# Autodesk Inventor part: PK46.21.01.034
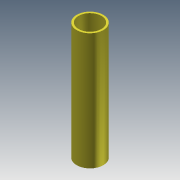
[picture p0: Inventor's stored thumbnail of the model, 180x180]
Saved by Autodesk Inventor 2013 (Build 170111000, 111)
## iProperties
Created: 2005-04
Part Number: PK46.21.01.034
Material: Steel, Mild
Document SubType Name: Modeling
Designer: salex
Manufacturer: Standard
Standards Organization: Custom
Density: 7.86 g/cm^3
Author: salex
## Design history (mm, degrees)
sketch "Эскиз1"
  geometry: C1 r 25 at (0, 0); C2 r 21.5 at (0, 0)
  constraints: 2 centre point, 1 coincident, 1 other
  dimensions: "d0" = 50 diameter of C1; "d1" = 3.5 radial gap between concentric circles of C1 C2
extrude "Выдавливание1" new body sketch "Эскиз1" distance "d2" = 220; taper "d3" = 0 deg
body "Solid1"
